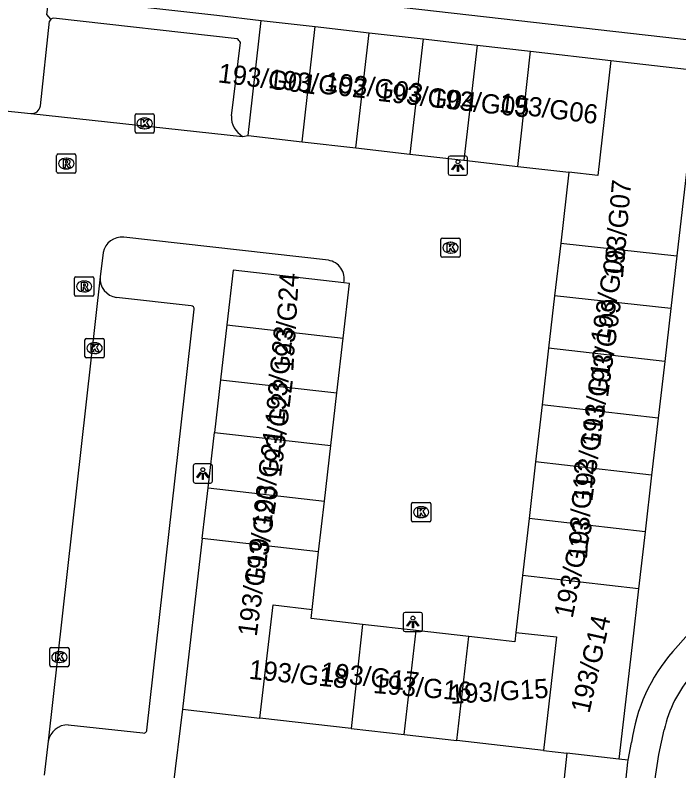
# Model space of a CAD drawing. Extents: x 162026 to 163499, y 387297 to 388169.
# Drawn here: x 162124.61 to 162159.1, y 387636.4 to 387675.7 of the extents above; entities that cross this region are included whole.
import ezdxf

# ---------------------------------------------------------------- set-up
doc = ezdxf.new("R2010")
doc.units = 0
for name, color, linetype in [('IMGEO_Groenvoorziening', 7, 'Continuous'), ('IMGEO_Kolk', 7, 'Continuous'), ('IMGEO_Lichtpunt', 7, 'Continuous'), ('IMGEO_Pand', 7, 'Continuous'), ('IMGEO_Pand_nummerreeks', 7, 'Continuous'), ('IMGEO_Parkeervlak_open', 7, 'Continuous'), ('IMGEO_Rijbaan_lokaal_open', 7, 'Continuous'), ('IMGEO_Rioolput', 7, 'Continuous'), ('IMGEO_Voetpad_open', 7, 'Continuous')]:
    doc.layers.add(name, color=color, linetype=linetype)

msp = doc.modelspace()

# ---------------------------------------------------------------- linework, layer by layer
at = {"layer": 'IMGEO_Groenvoorziening'}
msp.add_lwpolyline([(162156.469, 387636.953), (162155.986, 387637.005)], dxfattribs=at)
at = {"layer": 'IMGEO_Kolk'}
for p, q in [((162130.915, 387670.57), (162131.767, 387670.57)), ((162130.84, 387669.644), (162130.84, 387670.496)), ((162131.328, 387670.35), (162131.353, 387670.35)), ((162131.841, 387670.496), (162131.841, 387669.644)), ((162131.351, 387669.79), (162131.326, 387669.79)), ((162131.767, 387669.57), (162130.915, 387669.57)), ((162146.734, 387663.184), (162146.734, 387664.036)), ((162146.809, 387664.11), (162147.661, 387664.11)), ((162147.222, 387663.89), (162147.247, 387663.89)), ((162147.735, 387664.036), (162147.735, 387663.184)), ((162147.661, 387663.11), (162146.809, 387663.11)), ((162147.245, 387663.33), (162147.22, 387663.33)), ((162128.238, 387657.959), (162128.238, 387658.811)), ((162128.313, 387658.885), (162129.165, 387658.885)), ((162129.239, 387658.811), (162129.239, 387657.959)), ((162128.726, 387658.665), (162128.751, 387658.665)), ((162128.749, 387658.105), (162128.724, 387658.105)), ((162129.165, 387657.885), (162128.313, 387657.885)), ((162145.209, 387649.43), (162145.209, 387650.282)), ((162145.284, 387650.356), (162146.136, 387650.356)), ((162145.697, 387650.136), (162145.722, 387650.136)), ((162146.21, 387650.282), (162146.21, 387649.43)), ((162146.136, 387649.356), (162145.284, 387649.356)), ((162145.72, 387649.576), (162145.695, 387649.576)), ((162126.409, 387641.893), (162126.409, 387642.745)), ((162126.484, 387642.819), (162127.336, 387642.819)), ((162127.41, 387642.745), (162127.41, 387641.893)), ((162126.897, 387642.599), (162126.922, 387642.599)), ((162127.336, 387641.819), (162126.484, 387641.819)), ((162126.92, 387642.039), (162126.895, 387642.039))]:
    msp.add_line(p, q, dxfattribs=at)
for points in [[(162130.915, 387670.57), (162131.767, 387670.57)], [(162130.84, 387669.644), (162130.84, 387670.496)], [(162131.161, 387670.27), (162131.284, 387670.27), (162131.284, 387670.119), (162131.414, 387670.27), (162131.578, 387670.27), (162131.432, 387670.119), (162131.585, 387669.87), (162131.433, 387669.87), (162131.348, 387670.034), (162131.284, 387669.967), (162131.284, 387669.87), (162131.161, 387669.87), (162131.161, 387670.27)], [(162131.841, 387670.496), (162131.841, 387669.644)], [(162131.767, 387669.57), (162130.915, 387669.57)], [(162146.734, 387663.184), (162146.734, 387664.036)], [(162146.809, 387664.11), (162147.661, 387664.11)], [(162147.735, 387664.036), (162147.735, 387663.184)], [(162147.055, 387663.81), (162147.178, 387663.81), (162147.178, 387663.659), (162147.308, 387663.81), (162147.472, 387663.81), (162147.326, 387663.659), (162147.479, 387663.41), (162147.327, 387663.41), (162147.242, 387663.574), (162147.178, 387663.507), (162147.178, 387663.41), (162147.055, 387663.41), (162147.055, 387663.81)], [(162147.661, 387663.11), (162146.809, 387663.11)], [(162128.238, 387657.959), (162128.238, 387658.811)], [(162128.313, 387658.885), (162129.165, 387658.885)], [(162129.239, 387658.811), (162129.239, 387657.959)], [(162128.559, 387658.585), (162128.682, 387658.585), (162128.682, 387658.434), (162128.812, 387658.585), (162128.976, 387658.585), (162128.83, 387658.434), (162128.983, 387658.185), (162128.831, 387658.185), (162128.746, 387658.349), (162128.682, 387658.282), (162128.682, 387658.185), (162128.559, 387658.185), (162128.559, 387658.585)], [(162129.165, 387657.885), (162128.313, 387657.885)], [(162145.209, 387649.43), (162145.209, 387650.282)], [(162145.284, 387650.356), (162146.136, 387650.356)], [(162146.21, 387650.282), (162146.21, 387649.43)], [(162145.53, 387650.056), (162145.653, 387650.056), (162145.653, 387649.905), (162145.783, 387650.056), (162145.947, 387650.056), (162145.801, 387649.905), (162145.954, 387649.656), (162145.802, 387649.656), (162145.717, 387649.82), (162145.653, 387649.753), (162145.653, 387649.656), (162145.53, 387649.656), (162145.53, 387650.056)], [(162146.136, 387649.356), (162145.284, 387649.356)], [(162126.409, 387641.893), (162126.409, 387642.745)], [(162126.484, 387642.819), (162127.336, 387642.819)], [(162127.41, 387642.745), (162127.41, 387641.893)], [(162126.73, 387642.519), (162126.853, 387642.519), (162126.853, 387642.368), (162126.983, 387642.519), (162127.147, 387642.519), (162127.001, 387642.368), (162127.154, 387642.119), (162127.002, 387642.119), (162126.917, 387642.283), (162126.853, 387642.216), (162126.853, 387642.119), (162126.73, 387642.119), (162126.73, 387642.519)], [(162127.336, 387641.819), (162126.484, 387641.819)]]:
    msp.add_lwpolyline(points, dxfattribs=at)
for centre, start, end in [((162130.917, 387670.494), 91.552, 178.448), ((162130.917, 387670.494), 91.552, 178.448), ((162131.765, 387670.494), 1.552, 88.448), ((162131.765, 387670.494), 1.552, 88.448), ((162130.917, 387669.646), 181.552, 268.448), ((162130.917, 387669.646), 181.552, 268.448), ((162131.765, 387669.646), 271.552, 358.448), ((162131.765, 387669.646), 271.552, 358.448), ((162146.811, 387664.034), 91.552, 178.448), ((162146.811, 387664.034), 91.552, 178.448), ((162147.659, 387664.034), 1.552, 88.448), ((162147.659, 387664.034), 1.552, 88.448), ((162146.811, 387663.186), 181.552, 268.448), ((162146.811, 387663.186), 181.552, 268.448), ((162147.659, 387663.186), 271.552, 358.448), ((162147.659, 387663.186), 271.552, 358.448), ((162128.315, 387658.809), 91.552, 178.448), ((162128.315, 387658.809), 91.552, 178.448), ((162129.163, 387658.809), 1.552, 88.448), ((162129.163, 387658.809), 1.552, 88.448), ((162128.315, 387657.961), 181.552, 268.448), ((162128.315, 387657.961), 181.552, 268.448), ((162129.163, 387657.961), 271.552, 358.448), ((162129.163, 387657.961), 271.552, 358.448), ((162145.286, 387650.28), 91.552, 178.448), ((162145.286, 387650.28), 91.552, 178.448), ((162146.134, 387650.28), 1.552, 88.448), ((162146.134, 387650.28), 1.552, 88.448), ((162145.286, 387649.432), 181.552, 268.448), ((162145.286, 387649.432), 181.552, 268.448), ((162146.134, 387649.432), 271.552, 358.448), ((162146.134, 387649.432), 271.552, 358.448), ((162126.486, 387642.743), 91.552, 178.448), ((162126.486, 387642.743), 91.552, 178.448), ((162127.334, 387642.743), 1.552, 88.448), ((162127.334, 387642.743), 1.552, 88.448), ((162126.486, 387641.895), 181.552, 268.448), ((162126.486, 387641.895), 181.552, 268.448), ((162127.334, 387641.895), 271.552, 358.448), ((162127.334, 387641.895), 271.552, 358.448)]:
    msp.add_arc(centre, 0.0765, start, end, dxfattribs=at)
for centre, major_axis, ratio, start_param, end_param in [((162131.327, 387670.07), (-0.387, 0.002), 0.722429, 4.712389, 7.853982), ((162131.352, 387670.07), (-0.39, 0.002), 0.717154, 1.570796, 4.712389), ((162147.221, 387663.61), (-0.387, 0.002), 0.722429, 4.712389, 7.853982), ((162147.246, 387663.61), (-0.39, 0.002), 0.717154, 1.570796, 4.712389), ((162128.725, 387658.385), (-0.387, 0.002), 0.722429, 4.712389, 7.853982), ((162128.75, 387658.385), (-0.39, 0.002), 0.717154, 1.570796, 4.712389), ((162145.696, 387649.856), (-0.387, 0.002), 0.722429, 4.712389, 7.853982), ((162145.721, 387649.856), (-0.39, 0.002), 0.717154, 1.570796, 4.712389), ((162126.896, 387642.319), (-0.387, 0.002), 0.722429, 4.712389, 7.853982), ((162126.921, 387642.319), (-0.39, 0.002), 0.717154, 1.570796, 4.712389)]:
    msp.add_ellipse(centre, major_axis=major_axis, ratio=ratio, start_param=start_param, end_param=end_param, dxfattribs=at)
at = {"layer": 'IMGEO_Lichtpunt'}
for p, q in [((162147.12, 387668.28), (162147.12, 387667.473)), ((162147.12, 387668.28), (162147.12, 387667.473)), ((162148.022, 387668.375), (162147.214, 387668.375)), ((162148.022, 387668.375), (162147.214, 387668.375)), ((162148.116, 387667.473), (162148.116, 387668.28)), ((162148.116, 387667.473), (162148.116, 387668.28)), ((162147.214, 387667.379), (162148.022, 387667.379)), ((162147.214, 387667.379), (162148.022, 387667.379)), ((162133.865, 387652.268), (162133.865, 387651.461)), ((162133.865, 387652.268), (162133.865, 387651.461)), ((162134.767, 387652.363), (162133.959, 387652.363)), ((162134.767, 387652.363), (162133.959, 387652.363)), ((162134.861, 387651.461), (162134.861, 387652.268)), ((162134.861, 387651.461), (162134.861, 387652.268)), ((162133.959, 387651.367), (162134.767, 387651.367)), ((162133.959, 387651.367), (162134.767, 387651.367)), ((162145.683, 387644.644), (162144.875, 387644.644)), ((162145.683, 387644.644), (162144.875, 387644.644)), ((162144.781, 387644.549), (162144.781, 387643.742)), ((162144.781, 387644.549), (162144.781, 387643.742)), ((162145.777, 387643.742), (162145.777, 387644.549)), ((162145.777, 387643.742), (162145.777, 387644.549)), ((162144.875, 387643.648), (162145.683, 387643.648)), ((162144.875, 387643.648), (162145.683, 387643.648))]:
    msp.add_line(p, q, dxfattribs=at)
for points in [[(162147.494, 387667.944), (162147.533, 387667.916), (162147.345, 387667.654), (162147.307, 387667.681), (162147.494, 387667.944)], [(162147.596, 387667.896), (162147.643, 387667.896), (162147.643, 387667.574), (162147.596, 387667.574), (162147.596, 387667.896)], [(162147.706, 387667.916), (162147.744, 387667.943), (162147.931, 387667.681), (162147.892, 387667.653), (162147.706, 387667.916)], [(162134.239, 387651.932), (162134.278, 387651.904), (162134.09, 387651.642), (162134.052, 387651.669), (162134.239, 387651.932)], [(162134.341, 387651.884), (162134.388, 387651.884), (162134.388, 387651.562), (162134.341, 387651.562), (162134.341, 387651.884)], [(162134.451, 387651.904), (162134.489, 387651.931), (162134.676, 387651.669), (162134.637, 387651.641), (162134.451, 387651.904)], [(162145.155, 387644.213), (162145.194, 387644.185), (162145.006, 387643.923), (162144.968, 387643.95), (162145.155, 387644.213)], [(162145.367, 387644.185), (162145.405, 387644.212), (162145.592, 387643.95), (162145.553, 387643.922), (162145.367, 387644.185)], [(162145.257, 387644.165), (162145.304, 387644.165), (162145.304, 387643.843), (162145.257, 387643.843), (162145.257, 387644.165)]]:
    msp.add_lwpolyline(points, dxfattribs=at)
for centre in [(162147.619, 387668.078), (162134.364, 387652.066), (162145.28, 387644.347)]:
    msp.add_circle(centre, 0.0994, dxfattribs=at)
for centre, start, end in [((162147.214, 387668.28), 90, 180), ((162147.214, 387668.28), 90, 180), ((162148.022, 387668.28), 0, 90), ((162148.022, 387668.28), 0, 90), ((162147.214, 387667.473), 180, 270), ((162147.214, 387667.473), 180, 270), ((162148.022, 387667.473), 270, 0), ((162148.022, 387667.473), 270, 360), ((162133.959, 387652.268), 90, 180), ((162133.959, 387652.268), 90, 180), ((162134.767, 387652.268), 0, 90), ((162134.767, 387652.268), 0, 90), ((162133.959, 387651.461), 180, 270), ((162133.959, 387651.461), 180, 270), ((162134.767, 387651.461), 270, 0), ((162134.767, 387651.461), 270, 360), ((162144.875, 387644.549), 90, 180), ((162144.875, 387644.549), 90, 180), ((162145.683, 387644.549), 0, 90), ((162145.683, 387644.549), 0, 90), ((162144.875, 387643.742), 180, 270), ((162144.875, 387643.742), 180, 270), ((162145.683, 387643.742), 270, 0), ((162145.683, 387643.742), 270, 360)]:
    msp.add_arc(centre, 0.0946, start, end, dxfattribs=at)
at = {"layer": 'IMGEO_Pand'}
for points in [[(162136.713, 387669.445), (162137.401, 387675.431)], [(162137.401, 387675.431), (162140.205, 387675.109)], [(162139.517, 387669.123), (162140.205, 387675.109)], [(162140.205, 387675.109), (162143.008, 387674.786)], [(162142.321, 387668.801), (162143.008, 387674.786)], [(162143.008, 387674.786), (162145.812, 387674.464)], [(162145.812, 387674.464), (162145.124, 387668.478)], [(162145.812, 387674.464), (162148.616, 387674.142)], [(162148.616, 387674.142), (162147.928, 387668.156)], [(162148.616, 387674.142), (162151.388, 387673.823)], [(162150.732, 387667.834), (162151.388, 387673.823)], [(162151.388, 387673.823), (162155.57, 387673.343)], [(162155.57, 387673.343), (162154.882, 387667.357), (162153.383, 387667.529)], [(162155.57, 387673.343), (162160.102, 387672.822)], [(162160.102, 387672.822), (162158.995, 387663.193)], [(162136.713, 387669.445), (162139.517, 387669.123)], [(162139.517, 387669.123), (162142.321, 387668.801)], [(162142.321, 387668.801), (162145.124, 387668.478)], [(162145.124, 387668.478), (162147.928, 387668.156)], [(162147.928, 387668.156), (162150.732, 387667.834)], [(162150.732, 387667.834), (162153.383, 387667.529)], [(162153.383, 387667.529), (162152.96, 387663.846)], [(162152.96, 387663.846), (162152.644, 387661.104)], [(162152.96, 387663.846), (162158.995, 387663.193)], [(162158.995, 387663.193), (162158.679, 387660.441)], [(162141.688, 387661.781), (162135.935, 387662.443), (162135.608, 387659.593)], [(162141.66, 387658.898), (162141.987, 387661.747), (162141.688, 387661.781)], [(162152.644, 387661.104), (162152.331, 387658.382)], [(162158.679, 387660.441), (162152.644, 387661.104)], [(162158.679, 387660.441), (162158.364, 387657.699)], [(162135.608, 387659.593), (162135.28, 387656.743)], [(162135.608, 387659.593), (162141.66, 387658.898)], [(162141.333, 387656.056), (162141.66, 387658.898)], [(162152.331, 387658.382), (162151.992, 387655.436)], [(162158.364, 387657.699), (162152.331, 387658.382)], [(162158.364, 387657.699), (162158.024, 387654.743)], [(162135.28, 387656.743), (162134.965, 387654.001)], [(162135.28, 387656.743), (162141.333, 387656.056)], [(162141.019, 387653.325), (162141.333, 387656.056)], [(162151.992, 387655.436), (162151.653, 387652.48)], [(162158.024, 387654.743), (162151.992, 387655.436)], [(162158.024, 387654.743), (162157.685, 387651.786)], [(162134.634, 387651.123), (162134.965, 387654.001)], [(162134.965, 387654.001), (162141.019, 387653.325)], [(162140.686, 387650.427), (162141.019, 387653.325)], [(162151.653, 387652.48), (162151.313, 387649.523)], [(162157.685, 387651.786), (162151.653, 387652.48)], [(162157.685, 387651.786), (162157.345, 387648.83)], [(162134.33, 387648.479), (162134.634, 387651.123)], [(162134.634, 387651.123), (162140.686, 387650.427)], [(162140.382, 387647.784), (162140.686, 387650.427)], [(162151.313, 387649.523), (162150.973, 387646.567)], [(162157.345, 387648.83), (162151.313, 387649.523)], [(162157.345, 387648.83), (162157.005, 387645.874)], [(162134.33, 387648.479), (162133.311, 387639.611)], [(162140.382, 387647.784), (162134.33, 387648.479)], [(162140.039, 387644.801), (162140.382, 387647.784)], [(162150.973, 387646.567), (162150.632, 387643.598)], [(162157.005, 387645.874), (162150.973, 387646.567)], [(162157.005, 387645.874), (162156.67, 387642.954), (162155.986, 387637.005)], [(162137.334, 387639.149), (162138.01, 387645.03), (162140.039, 387644.801)], [(162142.669, 387644.019), (162139.985, 387644.328), (162140.039, 387644.801)], [(162142.669, 387644.019), (162142.079, 387638.603)], [(162145.445, 387643.7), (162142.669, 387644.019)], [(162144.823, 387638.288), (162145.445, 387643.7)], [(162148.184, 387643.385), (162145.445, 387643.7)], [(162150.632, 387643.598), (162150.576, 387643.11), (162148.184, 387643.385)], [(162150.632, 387643.598), (162152.748, 387643.369), (162152.069, 387637.455)], [(162147.567, 387637.973), (162148.184, 387643.385)], [(162133.311, 387639.611), (162137.334, 387639.149)], [(162142.079, 387638.603), (162137.334, 387639.149)], [(162142.079, 387638.603), (162144.823, 387638.288)], [(162144.823, 387638.288), (162147.567, 387637.973)], [(162152.069, 387637.455), (162147.567, 387637.973)], [(162152.069, 387637.455), (162153.283, 387637.316)], [(162155.986, 387637.005), (162153.283, 387637.316)]]:
    msp.add_lwpolyline(points, dxfattribs=at)
at = {"layer": 'IMGEO_Parkeervlak_open'}
for points in [[(162136.14, 387674.474), (162126.596, 387675.552)], [(162135.856, 387670.462), (162136.314, 387674.281)], [(162133.76, 387660.588), (162129.877, 387661.024)], [(162131.452, 387638.516), (162133.919, 387660.407)], [(162133.311, 387639.611), (162132.796, 387635.52)], [(162127.374, 387638.8), (162131.238, 387638.379)], [(162153.283, 387637.316), (162152.839, 387633.26)]]:
    msp.add_lwpolyline(points, dxfattribs=at)
for centre, radius, start, end in [((162126.615, 387675.336), 0.217, 95.0666, 131.6621), ((162135.934, 387674.113), 0.415, 23.8023, 60.2704), ((162136.976, 387670.382), 1.123, 175.8945, 240.9705), ((162130.014, 387662.007), 0.993, 175.4329, 262.0444), ((162133.736, 387660.406), 0.183, 0.2038, 82.3918), ((162127.371, 387637.729), 1.071, 89.8338, 168.3703), ((162131.293, 387638.529), 0.16, 250.0263, 355.2274)]:
    msp.add_arc(centre, radius, start, end, dxfattribs=at)
at = {"layer": 'IMGEO_Rijbaan_lokaal_open'}
for points in [[(162123.744, 387670.768), (162125.425, 387670.584)], [(162125.425, 387670.584), (162136.431, 387669.4)], [(162136.431, 387669.4), (162136.713, 387669.445)], [(162140.888, 387662.955), (162130.26, 387664.164)], [(162129.176, 387663.351), (162129.025, 387662.086)], [(162129.025, 387662.086), (162126.322, 387637.945)], [(162126.322, 387637.945), (162126.116, 387636.174)]]:
    msp.add_lwpolyline(points, dxfattribs=at)
for centre, radius, start, end in [((162130.169, 387663.156), 1.012, 84.8576, 168.8822), ((162140.739, 387661.994), 0.972, 347.3355, 81.208)]:
    msp.add_arc(centre, radius, start, end, dxfattribs=at)
at = {"layer": 'IMGEO_Rioolput'}
for p, q in [((162126.768, 387667.559), (162126.768, 387668.411)), ((162126.843, 387668.485), (162127.695, 387668.485)), ((162127.256, 387668.265), (162127.281, 387668.265)), ((162127.769, 387668.411), (162127.769, 387667.559)), ((162127.695, 387667.485), (162126.843, 387667.485)), ((162127.279, 387667.705), (162127.254, 387667.705)), ((162127.696, 387661.166), (162127.696, 387662.018)), ((162127.771, 387662.092), (162128.623, 387662.092)), ((162128.184, 387661.872), (162128.209, 387661.872)), ((162128.697, 387662.018), (162128.697, 387661.166)), ((162128.623, 387661.092), (162127.771, 387661.092)), ((162128.207, 387661.312), (162128.182, 387661.312))]:
    msp.add_line(p, q, dxfattribs=at)
for points in [[(162126.768, 387667.559), (162126.768, 387668.411)], [(162126.843, 387668.485), (162127.695, 387668.485)], [(162127.357, 387668.183), (162127.105, 387668.185), (162127.105, 387667.785)], [(162127.769, 387668.411), (162127.769, 387667.559)], [(162127.105, 387667.785), (162127.229, 387667.785), (162127.229, 387667.947), (162127.24, 387667.947)], [(162127.283, 387668.104), (162127.229, 387668.104), (162127.229, 387668.023)], [(162127.229, 387668.023), (162127.281, 387668.023)], [(162127.287, 387667.918), (162127.358, 387667.785), (162127.498, 387667.785), (162127.433, 387667.911)], [(162127.695, 387667.485), (162126.843, 387667.485)], [(162127.696, 387661.166), (162127.696, 387662.018)], [(162127.771, 387662.092), (162128.623, 387662.092)], [(162128.697, 387662.018), (162128.697, 387661.166)], [(162128.285, 387661.79), (162128.033, 387661.792), (162128.033, 387661.392)], [(162128.033, 387661.392), (162128.157, 387661.392), (162128.157, 387661.554), (162128.168, 387661.554)], [(162128.211, 387661.711), (162128.157, 387661.711), (162128.157, 387661.63)], [(162128.157, 387661.63), (162128.209, 387661.63)], [(162128.215, 387661.525), (162128.286, 387661.392), (162128.426, 387661.392), (162128.361, 387661.518)], [(162128.623, 387661.092), (162127.771, 387661.092)]]:
    msp.add_lwpolyline(points, dxfattribs=at)
for centre, radius, start, end in [((162126.845, 387668.409), 0.0765, 91.552, 178.448), ((162126.845, 387668.409), 0.0765, 91.552, 178.448), ((162127.356, 387668.073), 0.109, 350.3612, 89.416), ((162127.693, 387668.409), 0.0765, 1.552, 88.448), ((162127.693, 387668.409), 0.0765, 1.552, 88.448), ((162127.239, 387667.894), 0.0533, 26.0293, 88.6989), ((162127.265, 387668.212), 0.19, 274.7715, 282.9687), ((162127.289, 387668.008), 0.0964, 77.0061, 93.1865), ((162127.303, 387668.065), 0.0378, 276.6634, 79.6772), ((162127.354, 387668.073), 0.112, 277.5842, 350.9817), ((162127.338, 387667.858), 0.108, 29.5134, 73.7905), ((162126.845, 387667.561), 0.0765, 181.552, 268.448), ((162126.845, 387667.561), 0.0765, 181.552, 268.448), ((162127.693, 387667.561), 0.0765, 271.552, 358.448), ((162127.693, 387667.561), 0.0765, 271.552, 358.448), ((162127.773, 387662.016), 0.0765, 91.552, 178.448), ((162127.773, 387662.016), 0.0765, 91.552, 178.448), ((162128.621, 387662.016), 0.0765, 1.552, 88.448), ((162128.621, 387662.016), 0.0765, 1.552, 88.448), ((162128.167, 387661.501), 0.0533, 26.0293, 88.6989), ((162128.193, 387661.819), 0.19, 274.7715, 282.9687), ((162128.217, 387661.615), 0.0964, 77.0061, 93.1865), ((162128.231, 387661.672), 0.0378, 276.6634, 79.6772), ((162128.284, 387661.68), 0.109, 350.3612, 89.416), ((162128.282, 387661.68), 0.112, 277.5842, 350.9817), ((162128.266, 387661.465), 0.108, 29.5134, 73.7905), ((162127.773, 387661.168), 0.0765, 181.552, 268.448), ((162127.773, 387661.168), 0.0765, 181.552, 268.448), ((162128.621, 387661.168), 0.0765, 271.552, 358.448), ((162128.621, 387661.168), 0.0765, 271.552, 358.448)]:
    msp.add_arc(centre, radius, start, end, dxfattribs=at)
for centre, major_axis, ratio, start_param, end_param in [((162127.255, 387667.985), (-0.387, 0.002), 0.722429, 4.712389, 7.853982), ((162127.28, 387667.985), (-0.39, 0.002), 0.717154, 1.570796, 4.712389), ((162128.183, 387661.592), (-0.387, 0.002), 0.722429, 4.712389, 7.853982), ((162128.208, 387661.592), (-0.39, 0.002), 0.717154, 1.570796, 4.712389)]:
    msp.add_ellipse(centre, major_axis=major_axis, ratio=ratio, start_param=start_param, end_param=end_param, dxfattribs=at)
at = {"layer": 'IMGEO_Voetpad_open'}
for points in [[(162105.439, 387680.558), (162106.116, 387680.474), (162126.346, 387678.207), (162159.943, 387674.378)], [(162126.471, 387675.498), (162126.257, 387675.744), (162126.381, 387676.687), (162135.089, 387675.71), (162137.401, 387675.431)], [(162125.92, 387670.978), (162126.403, 387675.387)], [(162158.78, 387642.608), (162162.327, 387646.601)], [(162158.944, 387632.737), (162157.532, 387632.884), (162157.852, 387635.878), (162158.057, 387637.248), (162158.34, 387638.537)], [(162156.469, 387636.953), (162156.644, 387637.881)], [(162155.942, 387631.988), (162156.451, 387636.858), (162156.469, 387636.953)]]:
    msp.add_lwpolyline(points, dxfattribs=at)
for centre, radius, start, end in [((162126.629, 387675.325), 0.235, 132.4102, 164.6055), ((162125.468, 387671.038), 0.456, 264.5637, 352.473), ((162165.593, 387636.683), 9.029, 138.9887, 172.3775), ((162164.709, 387637.133), 6.522, 139.0934, 167.5689)]:
    msp.add_arc(centre, radius, start, end, dxfattribs=at)

# ---------------------------------------------------------------- texts
at = {"layer": 'IMGEO_Pand_nummerreeks'}
for s, rotation, p in [('193/G01', 352.875, (162135.118, 387672.214)), ('193/G02', 353.9275, (162137.727, 387671.916)), ('193/G03', 352.7468, (162140.646, 387671.776)), ('193/G04', 353.5412, (162143.409, 387671.249)), ('193/G05', 353.6598, (162146.18, 387670.936)), ('193/G06', 352.875, (162149.736, 387670.673)), ('193/G07', 85.1009, (162156.192, 387661.982)), ('193/G08', 80.1807, (162155.484, 387658.583)), ('193/G24', 86.7, (162139.063, 387657.151)), ('193/G09', 82.1847, (162155.415, 387655.793)), ('193/G23', 84.6107, (162138.589, 387654.373)), ('193/G10', 82.7468, (162155.006, 387653.217)), ('193/G22', 83.0189, (162138.425, 387651.644)), ('193/G11', 82.4762, (162154.598, 387650.384)), ('193/G21', 82.9987, (162137.904, 387649.009)), ('193/G12', 85.8404, (162154.322, 387647.384)), ('193/G20', 81.4164, (162137.526, 387646.079)), ('193/G13', 78.2749, (162153.575, 387644.301)), ('193/G19', 82.4762, (162137.16, 387643.357)), ('193/G14', 77.4696, (162154.446, 387639.355)), ('193/G18', 354.3518, (162136.725, 387641.192)), ('193/G17', 353.7742, (162140.447, 387641.08)), ('193/G16', 355.1355, (162143.184, 387640.455)), ('193/G15', 3.6215, (162147.231, 387639.882))]:
    msp.add_text(s, height=1, rotation=rotation, dxfattribs=at).set_placement(p)

doc.saveas('drawing.dxf')
